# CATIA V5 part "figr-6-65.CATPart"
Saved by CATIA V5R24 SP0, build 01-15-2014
Part number: Part1
Bounding box of the stored display mesh (mm): x -50.648 to 96.836, y -72.183 to 72.183, z -40 to 40
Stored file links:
  D:\KAVITA\CATIA V5-6R2014 Project_ Kavita\CATIA V5-6R2014_partfiles\Partfiles\c06_catia_v5-6r2014_prt\figr-6-65.CATPart
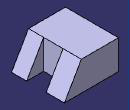
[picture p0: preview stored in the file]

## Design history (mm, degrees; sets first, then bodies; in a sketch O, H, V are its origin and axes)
Set1
  Plane1: type Offset, RefPlane face of Pad1, Offset -50, reversed
  Plane2: type Offset, RefPlane Plane1, Offset 53
Body1 (main body)
  Sketch1 on xy-plane, origin (0, 0, 0), H (1, 0, 0), V (0, 1, 0)
    line L1 (-50.6478, 72.1832) -> (50.6478, 72.1832)
    line L2 (50.6478, 72.1832) -> (50.6478, -72.1832)
    line L3 (50.6478, -72.1832) -> (-50.6478, -72.1832)
    line L4 (-50.6478, -72.1832) -> (-50.6478, 72.1832)
    axis line L5 (50.6478, -72.1832) -> (-50.6478, 72.1832)
    horizontal: L1 H, L3 H
    vertical: L2 V, L4 V
    midpoint: O L5
  Pad1: profile Sketch1, direction (0, 0, 1), length 40, mirrored extent
  Draft1: Angle 30, Neutral face of Pad1, PullDir (0, 0, 1), SupportToDraft face of Pad1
